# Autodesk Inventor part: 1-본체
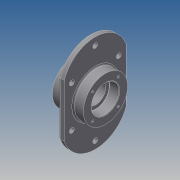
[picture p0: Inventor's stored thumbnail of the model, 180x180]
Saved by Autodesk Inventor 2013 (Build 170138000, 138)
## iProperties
Created: 2015-02
Part Number: 1-본체
Material: Generic
Document SubType Name: Modeling
Designer: kb146
Density: 1 g/cm^3
Author: kb146
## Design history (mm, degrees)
sketch "스케치2"
  geometry: L1 (-35, 31)-(-35, 50); L2 (-35, 50)-(35, 50); L3 (35, 50)-(35, 31); L4 (35, 31)-(13, 31); L5 (13, 31)-(13, 22.5); L6 (13, 22.5)-(-13, 22.5); L7 (-13, 22.5)-(-13, 31); L8 (-13, 31)-(-35, 31); L9 (-35, 0)-(35, 0); 2 further points
  constraints: 18 end point, 6 parallel, 2 vertical, 2 vertical alignment, 1 coincident, 1 midpoint, 1 perpendicular
  dimensions: "d0" = 62 diameter of L8 L9; "d2" = 45 diameter of L6 L9; "d3" = 62 diameter of L4 L9; "d4" = 100 diameter of L2 L9; "d5" = 22 distance of L7.end L1.start; "d6" = 22 distance of L3.end L4.end; "d7" = 70 distance of L1.end L2.end
revolve "회전1" sketch "스케치2" stored, may be unused: angle "d8" = 90 deg
node "작업 평면1"
sketch "스케치4"
  geometry: L1 (-70, 60)-(70, 60); L2 (70, 60)-(70, -60); L3 (70, -60)-(-70, -60); L4 (-70, -60)-(-70, 60); L5 (-70, 60)-(70, -60); L6 (70, 60)-(-70, -60); L7 (0, 110)-(0, -110); C1 r 31 at (0, 0) reference; A1 r 74 centre (0, 36) between (70, 60) and (-70, 60); A2 r 74 centre (0, -36) between (-70, -60) and (70, -60); 1 further point
  constraints: 14 end point, 6 point on circle, 2 centre point, 2 midpoint, 2 parallel, 1 equal radius, 1 horizontal, 1 perpendicular
  dimensions: "d10" = 120 distance of L1.end L2.end; "d12" = 140 distance of L1.start L1.end; "d13" = 220 dimension on A2 A1
extrude "돌출1" join sketch "스케치4" distance "d14" = 12; taper "d15" = 0 deg
sketch "스케치5"
  geometry: L1 (60, 70)-(-60, 70) reference; L2 (-60, -70)-(60, -70) reference; L3 (-56.976, 53)-(56.976, 53); L4 (56.976, -53)-(-56.976, -53); L5 (-93, 0)-(93, 0); L6 (-46.5, 53)-(-46.5, -53); L7 (46.5, 53)-(46.5, -53); L8 (62, -53)-(62, 53); L9 (-62, 53)-(-62, -53); C1 r 10 at (-46.5, 53); C2 r 10 at (-93, 0); C3 r 10 at (46.5, 53); C4 r 10 at (-46.5, -53); C5 r 10 at (46.5, -53); C6 r 10 at (93, 0); C7 r 5.5 at (-93, 0); C8 r 5.5 at (-46.5, 53); C9 r 5.5 at (46.5, 53); C10 r 5.5 at (93, 0); C11 r 5.5 at (46.5, -53); C12 r 5.5 at (-46.5, -53); A1 r 74 centre (36, 0) between (60, -70) and (60, 70) reference; A2 r 74 centre (-36, 0) between (-60, 70) and (-60, -70) reference; A3 r 57 centre (36, 0) between (56.976, -53) and (56.976, 53); A4 r 57 centre (-36, 0) between (-56.976, 53) and (-56.976, -53)
  constraints: 14 centre point, 14 end point, 12 coincident, 8 point on line, 6 point on circle, 5 equal radius, 4 perpendicular, 3 other
  dimensions: "d16" = 17 distance between parallel lines of L3 L1; "d19" = 20 diameter of C2; "d20" = 20 diameter of C3; "d21" = 20 diameter of C4; "d22" = 20 diameter of C5; "d23" = 20 diameter of C6; "d24" = 20 diameter of C1; "d30" = 11 diameter of C12; "d63" = 31 horizontal distance of L8.start L5.end; "d64" = 31 horizontal distance of L9.end L5.start; "d65" = 15.5 distance of L8.start L7.end; "d66" = 15.5 distance of L9.end L6.end
extrude "돌출2" join sketch "스케치5" distance "d31" = 5; taper "d32" = 0 deg
extrude "돌출3" cut sketch "스케치5" stored distance "d33" = 5; taper "d34" = 0 deg
sketch "스케치6"
  geometry: C1 r 22.5 at (0, 0) reference; C2 r 22.5 at (0, 0)
  constraints: 1 centre point, 1 coincident
  dimensions: "d35" = 45 diameter of C2
extrude "돌출4" cut sketch "스케치6" stored distance "d37" = 5; taper "d38" = 0 deg
sketch "스케치7"
  geometry: L1 (0, 0)-(-41, 0); L2 (0, 0)-(-28.991, 28.991); C1 r 50 at (0, 0) reference; C2 r 22.5 at (0, 0) reference; A1 r 41 centre (0, 0) between (-41, 0) and (-28.991, 28.991); 1 further point
  constraints: 4 end point, 2 coincident, 2 point on circle, 1 centre point, 1 horizontal
  dimensions: "d39" = 82 diameter of A1; "d40" = 45 deg angle of L2 L1
hole "구멍1" sketch "스케치7" at (-28.991, 28.991) diameter "d42" = 4.917; stored, may be unused: countersink angle "d46" = 90 deg, drill point angle "d48" = 118 deg; dims "d43" = 10, "d44" = 4, "d45" = 2, "d47" = 13
sketch "스케치8"
  geometry: C1 r 50 at (0, 0) reference; 1 further point
  constraints: 1 horizontal alignment, 1 other
  dimensions: "d52" = 65 distance of C1.centre point (65, 0)
feature "엠보싱1" sketch "스케치8" dims "d0" = 62, "d2" = 45, "d3" = 62, "d4" = 100, "d5" = 22, "d6" = 22, "d7" = 70, "d53" = 1, "d54" = 0
fillet "모깎기1" dims "d55" = 3, "d56" = 0.3
chamfer "모따기1" distance "d57" = 1; stored, may be unused: second distance "d58" = 2, angle "d59" = 45 deg
node "솔리드1"
pattern_circular "원형 패턴1" dims angle "d50" = 360 deg
mirror "대칭1"
other parameters: "d9" = -23
